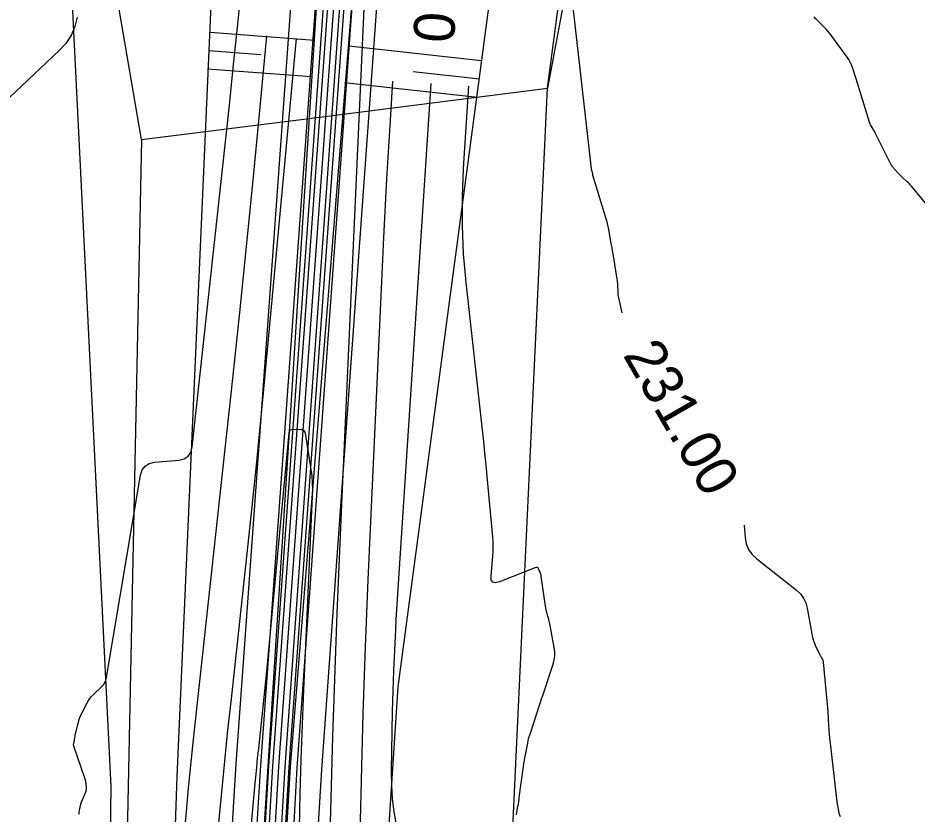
# Model space of a CAD drawing. Extents: x -534410 to -534262, y -1190162 to -1189584.
# Drawn here: x -534369.58 to -534347.56, y -1189654.72 to -1189635.21 of the extents above; entities that cross this region are included whole.
import ezdxf

# ---------------------------------------------------------------- set-up
doc = ezdxf.new("R2010")
doc.units = 0
for name, color, linetype in [('30', 7, 'Continuous'), ('31', 7, 'Continuous'), ('40', 7, 'Continuous'), ('_linie', 7, 'Continuous'), ('_N_osa', 7, 'Continuous'), ('_N_tenká', 7, 'Continuous'), ('_N_tenká_velmi', 7, 'Continuous'), ('_tenka', 7, 'Continuous'), ('_velmi_tenka', 7, 'Continuous'), ('Default', 7, 'Continuous'), ('Hranice parcel', 7, 'Continuous')]:
    doc.layers.add(name, color=color, linetype=linetype)

msp = doc.modelspace()

# ---------------------------------------------------------------- linework, layer by layer
at = {"layer": '30'}
for points in [[(-534356.77, -1189628.102), (-534355.551, -1189638.836), (-534355.548, -1189638.861), (-534355.544, -1189638.886), (-534355.54, -1189638.911), (-534355.534, -1189638.936), (-534355.512, -1189639.036), (-534355.507, -1189639.061), (-534355.5, -1189639.086), (-534355.494, -1189639.111), (-534355.486, -1189639.135), (-534355.19, -1189640.102), (-534355.169, -1189640.175), (-534355.15, -1189640.248), (-534355.134, -1189640.322), (-534355.119, -1189640.397), (-534355.066, -1189640.695), (-534355.053, -1189640.77), (-534355.04, -1189640.845), (-534355.028, -1189640.919), (-534355.015, -1189640.994), (-534354.914, -1189641.61), (-534354.909, -1189641.648), (-534354.904, -1189641.686), (-534354.901, -1189641.724), (-534354.899, -1189641.762), (-534354.893, -1189641.915), (-534354.891, -1189641.953), (-534354.887, -1189641.991), (-534354.881, -1189642.029), (-534354.874, -1189642.066), (-534354.791, -1189642.439)], [(-534361.953, -1189655.843), (-534361.869, -1189652.815), (-534361.764, -1189649.788), (-534361.638, -1189646.761), (-534360.829, -1189628.817)], [(-534368.091, -1189654.72), (-534368.087, -1189654.7), (-534368.084, -1189654.68), (-534368.066, -1189654.581), (-534368.061, -1189654.558), (-534368.057, -1189654.536), (-534368.047, -1189654.49), (-534368.044, -1189654.479), (-534368.041, -1189654.468), (-534368.037, -1189654.457), (-534368.033, -1189654.446), (-534367.919, -1189654.177), (-534367.911, -1189654.152), (-534367.905, -1189654.127), (-534367.903, -1189654.101), (-534367.904, -1189654.075), (-534367.916, -1189653.968), (-534367.919, -1189653.941), (-534367.924, -1189653.915), (-534367.931, -1189653.889), (-534367.939, -1189653.864), (-534368.214, -1189653.052), (-534368.218, -1189653.036), (-534368.22, -1189653.02), (-534368.22, -1189653.004), (-534368.218, -1189652.987), (-534368.202, -1189652.913), (-534368.2, -1189652.9), (-534368.198, -1189652.888), (-534368.196, -1189652.875), (-534368.194, -1189652.862), (-534368.187, -1189652.811), (-534368.185, -1189652.798), (-534368.183, -1189652.786), (-534368.18, -1189652.773), (-534368.177, -1189652.761), (-534368.099, -1189652.457), (-534368.083, -1189652.402), (-534368.065, -1189652.349), (-534368.043, -1189652.297), (-534368.019, -1189652.246), (-534367.891, -1189651.996), (-534367.858, -1189651.939), (-534367.822, -1189651.886), (-534367.781, -1189651.836), (-534367.735, -1189651.789), (-534367.534, -1189651.6), (-534367.489, -1189651.551), (-534367.454, -1189651.497), (-534367.428, -1189651.437), (-534367.412, -1189651.373), (-534366.581, -1189646.417), (-534366.541, -1189646.287), (-534366.47, -1189646.191), (-534366.368, -1189646.128), (-534366.236, -1189646.098), (-534365.644, -1189646.047), (-534365.512, -1189646.017), (-534365.414, -1189645.953), (-534365.348, -1189645.856), (-534365.316, -1189645.725), (-534364.406, -1189637.346), (-534364.301, -1189636.356), (-534364.199, -1189635.366), (-534364.1, -1189634.375)], [(-534362.766, -1189635.716), (-534363.58, -1189644.397), (-534363.668, -1189645.326), (-534363.76, -1189646.254), (-534363.856, -1189647.182), (-534363.955, -1189648.109), (-534364.357, -1189651.819), (-534364.456, -1189652.746), (-534364.55, -1189653.674), (-534364.64, -1189654.602), (-534364.726, -1189655.531)], [(-534359.474, -1189636.822), (-534360.283, -1189649.202), (-534360.298, -1189649.452), (-534360.313, -1189649.701), (-534360.326, -1189649.951), (-534360.338, -1189650.201), (-534360.383, -1189651.2), (-534360.393, -1189651.45), (-534360.402, -1189651.7), (-534360.409, -1189651.95), (-534360.414, -1189652.2), (-534360.439, -1189653.68), (-534360.436, -1189654.009), (-534360.415, -1189654.336), (-534360.376, -1189654.662), (-534360.319, -1189654.986)], [(-534351.799, -1189647.64), (-534351.772, -1189647.94), (-534351.743, -1189648.095), (-534351.686, -1189648.235), (-534351.6, -1189648.359), (-534351.485, -1189648.468), (-534350.515, -1189649.229), (-534350.417, -1189649.32), (-534350.34, -1189649.425), (-534350.284, -1189649.542), (-534350.248, -1189649.671), (-534350.118, -1189650.39), (-534350.107, -1189650.438), (-534350.093, -1189650.485), (-534350.076, -1189650.532), (-534350.056, -1189650.577), (-534349.939, -1189650.815), (-534349.931, -1189650.83), (-534349.924, -1189650.844), (-534349.916, -1189650.859), (-534349.908, -1189650.874), (-534349.876, -1189650.932), (-534349.868, -1189650.947), (-534349.863, -1189650.962), (-534349.859, -1189650.978), (-534349.856, -1189650.994), (-534349.755, -1189652.126), (-534349.749, -1189652.194), (-534349.744, -1189652.262), (-534349.739, -1189652.331), (-534349.734, -1189652.399), (-534349.71, -1189652.791), (-534349.709, -1189652.81), (-534349.707, -1189652.829), (-534349.704, -1189652.867), (-534349.702, -1189652.886), (-534349.7, -1189652.904), (-534349.525, -1189654.42), (-534349.512, -1189654.512), (-534349.495, -1189654.603), (-534349.473, -1189654.693), (-534349.446, -1189654.782)]]:
    msp.add_lwpolyline(points, dxfattribs=at)
at = {"layer": '31'}
for points in [[(-534368.133, -1189635.192), (-534368.19, -1189635.425), (-534368.283, -1189635.639), (-534368.409, -1189635.834), (-534368.571, -1189636.011), (-534371.025, -1189638.319)], [(-534347.156, -1189639.991), (-534347.694, -1189639.337), (-534347.719, -1189639.308), (-534347.745, -1189639.28), (-534347.772, -1189639.253), (-534347.8, -1189639.226), (-534347.913, -1189639.123), (-534347.942, -1189639.097), (-534347.969, -1189639.07), (-534347.996, -1189639.043), (-534348.022, -1189639.015), (-534348.125, -1189638.901), (-534348.149, -1189638.872), (-534348.172, -1189638.842), (-534348.192, -1189638.809), (-534348.211, -1189638.776), (-534348.587, -1189638.023), (-534348.598, -1189638.001), (-534348.609, -1189637.98), (-534348.622, -1189637.958), (-534348.634, -1189637.938), (-534348.685, -1189637.854), (-534348.698, -1189637.833), (-534348.708, -1189637.811), (-534348.718, -1189637.789), (-534348.726, -1189637.766), (-534348.99, -1189636.914), (-534349.055, -1189636.705), (-534349.142, -1189636.426), (-534349.166, -1189636.358), (-534349.196, -1189636.292), (-534349.231, -1189636.229), (-534349.272, -1189636.169), (-534349.671, -1189635.629), (-534349.708, -1189635.581), (-534349.746, -1189635.534), (-534349.787, -1189635.489), (-534349.828, -1189635.445), (-534350.007, -1189635.264), (-534350.045, -1189635.224), (-534350.082, -1189635.184)], [(-534365.595, -1189656.177), (-534365.451, -1189654.569), (-534365.414, -1189654.167), (-534365.375, -1189653.765), (-534365.334, -1189653.364), (-534365.291, -1189652.963), (-534364.324, -1189644.049), (-534364.151, -1189642.43), (-534363.984, -1189640.809), (-534363.824, -1189639.189), (-534363.669, -1189637.567), (-534363.489, -1189635.648)], [(-534360.41, -1189636.76), (-534360.47, -1189637.715), (-534360.553, -1189639.153), (-534360.629, -1189640.593), (-534360.697, -1189642.032), (-534361.011, -1189648.981), (-534361.079, -1189650.619), (-534361.135, -1189652.258), (-534361.181, -1189653.897), (-534361.215, -1189655.536)], [(-534357.374, -1189654.738), (-534357.336, -1189654.525), (-534357.327, -1189654.472), (-534357.318, -1189654.419), (-534357.31, -1189654.365), (-534357.303, -1189654.312), (-534357.199, -1189653.55), (-534357.189, -1189653.479), (-534357.177, -1189653.409), (-534357.165, -1189653.338), (-534357.152, -1189653.267), (-534357.097, -1189652.985), (-534357.083, -1189652.915), (-534357.066, -1189652.846), (-534357.046, -1189652.777), (-534357.025, -1189652.708), (-534356.741, -1189651.848), (-534356.737, -1189651.837), (-534356.475, -1189651.042), (-534356.448, -1189650.943), (-534356.435, -1189650.843), (-534356.435, -1189650.742), (-534356.448, -1189650.64), (-534356.549, -1189650.097), (-534356.556, -1189650.061), (-534356.564, -1189650.025), (-534356.573, -1189649.99), (-534356.583, -1189649.955), (-534356.623, -1189649.815), (-534356.633, -1189649.78), (-534356.641, -1189649.745), (-534356.648, -1189649.709), (-534356.654, -1189649.673), (-534356.767, -1189648.894), (-534356.771, -1189648.869), (-534356.777, -1189648.845), (-534356.785, -1189648.822), (-534356.793, -1189648.799), (-534356.832, -1189648.707), (-534356.843, -1189648.688), (-534356.858, -1189648.677), (-534356.876, -1189648.674), (-534356.897, -1189648.68), (-534357.792, -1189649.03), (-534357.888, -1189649.053), (-534357.954, -1189649.035), (-534357.989, -1189648.977), (-534357.994, -1189648.878), (-534357.952, -1189648.4), (-534357.944, -1189648.281), (-534357.941, -1189648.162), (-534357.944, -1189648.042), (-534357.953, -1189647.923), (-534358.089, -1189646.444), (-534358.116, -1189646.158), (-534358.144, -1189645.872), (-534358.174, -1189645.586), (-534358.205, -1189645.301), (-534358.606, -1189641.691), (-534358.668, -1189640.994), (-534358.699, -1189640.296), (-534358.699, -1189639.597), (-534358.669, -1189638.898), (-534358.538, -1189636.883)], [(-534365.3, -1189670.958), (-534363.781, -1189654.053), (-534363.759, -1189653.817), (-534363.737, -1189653.581), (-534363.713, -1189653.346), (-534363.688, -1189653.111), (-534363.586, -1189652.17), (-534363.56, -1189651.934), (-534363.536, -1189651.699), (-534363.513, -1189651.463), (-534363.49, -1189651.228), (-534362.943, -1189645.379), (-534362.933, -1189645.339), (-534362.913, -1189645.311), (-534362.883, -1189645.294), (-534362.842, -1189645.289), (-534362.659, -1189645.292), (-534362.618, -1189645.299), (-534362.586, -1189645.316), (-534362.565, -1189645.345), (-534362.553, -1189645.385), (-534362.411, -1189646.272), (-534362.389, -1189646.435), (-534362.375, -1189646.599), (-534362.37, -1189646.763), (-534362.374, -1189646.928), (-534362.588, -1189651.678), (-534362.623, -1189652.524), (-534362.652, -1189653.371), (-534362.676, -1189654.218), (-534362.693, -1189655.065)]]:
    msp.add_lwpolyline(points, dxfattribs=at)
at = {"layer": '_linie'}
for points in [[(-534366.12, -1189620.81), (-534364.52, -1189627.2), (-534365.69, -1189653.8), (-534366.76, -1189684.81), (-534368.14, -1189748.73), (-534368.38, -1189779.14), (-534368.65, -1189820.64), (-534368.59, -1189847.58), (-534367.2, -1189913.8)], [(-534363.12, -1189621.02), (-534362.79, -1189621.58), (-534361.82, -1189627.79), (-534363.46, -1189653.55), (-534365.47, -1189684.77), (-534366.65, -1189748.83), (-534366.75, -1189779.47), (-534366.9, -1189820.47), (-534366.95, -1189846.72), (-534366.338, -1189888.804), (-534363.85, -1189911.95), (-534357.07, -1189929.19), (-534352.334, -1189940.856)], [(-534359.03, -1189621.26), (-534359.41, -1189621.83), (-534360.84, -1189627.76), (-534362.92, -1189653.56), (-534364.64, -1189685), (-534365.94, -1189748.9), (-534366.02, -1189779.52), (-534366.03, -1189820.5), (-534366.48, -1189846.73), (-534365.511, -1189888.873), (-534362.72, -1189912.12), (-534356.62, -1189928.64), (-534351.589, -1189940.594)]]:
    msp.add_lwpolyline(points, dxfattribs=at)
at = {"layer": '_N_osa'}
msp.add_lwpolyline([(-534351.95, -1189940.722), (-534356.845, -1189928.915), (-534363.285, -1189912.035), (-534365.925, -1189888.838), (-534366.715, -1189846.725), (-534366.465, -1189820.485), (-534366.385, -1189779.495), (-534366.295, -1189748.865), (-534365.055, -1189684.885), (-534363.19, -1189653.555), (-534361.333, -1189627.822)], dxfattribs=at)
at = {"layer": '_N_tenká'}
for points in [[(-534352.92, -1189941.124), (-534357.821, -1189929.303), (-534364.313, -1189912.285), (-534366.973, -1189888.908), (-534367.765, -1189846.73), (-534367.515, -1189820.479), (-534367.435, -1189779.492), (-534367.345, -1189748.853), (-534366.104, -1189684.844), (-534364.238, -1189653.486), (-534362.424, -1189628.352), (-534361.782, -1189627.792)], [(-534350.98, -1189940.319), (-534355.869, -1189928.527), (-534362.257, -1189911.785), (-534364.876, -1189888.769), (-534365.665, -1189846.72), (-534365.415, -1189820.491), (-534365.335, -1189779.498), (-534365.245, -1189748.877), (-534364.006, -1189684.926), (-534362.142, -1189653.624), (-534360.329, -1189628.488), (-534360.884, -1189627.851)]]:
    msp.add_lwpolyline(points, dxfattribs=at)
at = {"layer": '_N_tenká_velmi'}
for points in [[(-534352.366, -1189940.894), (-534357.263, -1189929.081), (-534363.726, -1189912.142), (-534366.374, -1189888.868), (-534367.165, -1189846.727), (-534366.915, -1189820.482), (-534366.835, -1189779.494), (-534366.745, -1189748.86), (-534365.505, -1189684.867), (-534363.639, -1189653.525), (-534361.782, -1189627.792)], [(-534352.181, -1189940.817), (-534357.077, -1189929.007), (-534363.53, -1189912.095), (-534366.174, -1189888.855), (-534366.965, -1189846.726), (-534366.715, -1189820.484), (-534366.635, -1189779.494), (-534366.545, -1189748.862), (-534365.305, -1189684.875), (-534363.439, -1189653.539), (-534361.583, -1189627.805)], [(-534352.089, -1189940.779), (-534356.984, -1189928.97), (-534363.432, -1189912.071), (-534366.074, -1189888.848), (-534366.865, -1189846.726), (-534366.615, -1189820.484), (-534366.535, -1189779.495), (-534366.445, -1189748.863), (-534365.205, -1189684.879), (-534363.34, -1189653.545), (-534361.483, -1189627.812)], [(-534351.812, -1189940.664), (-534356.706, -1189928.86), (-534363.138, -1189911.999), (-534365.775, -1189888.828), (-534366.565, -1189846.724), (-534366.315, -1189820.486), (-534366.235, -1189779.495), (-534366.145, -1189748.867), (-534364.905, -1189684.891), (-534363.04, -1189653.565), (-534361.184, -1189627.831)], [(-534351.719, -1189940.626), (-534356.613, -1189928.823), (-534363.04, -1189911.975), (-534365.675, -1189888.822), (-534366.465, -1189846.724), (-534366.215, -1189820.486), (-534366.135, -1189779.496), (-534366.045, -1189748.868), (-534364.805, -1189684.895), (-534362.941, -1189653.571), (-534361.084, -1189627.838)], [(-534351.534, -1189940.549), (-534356.427, -1189928.749), (-534362.844, -1189911.928), (-534365.475, -1189888.808), (-534366.265, -1189846.723), (-534366.015, -1189820.488), (-534365.935, -1189779.496), (-534365.845, -1189748.87), (-534364.605, -1189684.903), (-534362.741, -1189653.585), (-534360.884, -1189627.851)]]:
    msp.add_lwpolyline(points, dxfattribs=at)
at = {"layer": '_tenka'}
for points in [[(-534349.13, -1189939.73), (-534354.63, -1189926.96), (-534362.03, -1189907.65), (-534364.521, -1189888.74), (-534364.47, -1189846.64), (-534364.29, -1189820.63), (-534364.22, -1189780.69), (-534363.18, -1189749.38), (-534362.5, -1189685.39), (-534360.27, -1189651.6), (-534357.03, -1189627.34), (-534354.77, -1189620.37)], [(-534366.12, -1189620.81), (-534364.52, -1189627.2), (-534365.69, -1189653.8), (-534366.76, -1189684.81), (-534368.14, -1189748.73), (-534368.38, -1189779.14), (-534368.65, -1189820.64), (-534368.59, -1189847.58), (-534367.2, -1189913.8)], [(-534366.12, -1189620.81), (-534364.52, -1189627.2), (-534365.69, -1189653.8), (-534366.76, -1189684.81), (-534368.14, -1189748.73), (-534368.38, -1189779.14), (-534368.65, -1189820.64), (-534368.59, -1189847.58), (-534367.2, -1189913.8)], [(-534363.12, -1189621.02), (-534362.79, -1189621.58), (-534361.82, -1189627.79), (-534363.46, -1189653.55), (-534365.47, -1189684.77), (-534366.65, -1189748.83), (-534366.75, -1189779.47), (-534366.9, -1189820.47), (-534366.95, -1189846.72), (-534366.338, -1189888.804), (-534363.85, -1189911.95), (-534357.07, -1189929.19), (-534352.334, -1189940.856)], [(-534363.12, -1189621.02), (-534362.79, -1189621.58), (-534361.82, -1189627.79), (-534363.46, -1189653.55), (-534365.47, -1189684.77), (-534366.65, -1189748.83), (-534366.75, -1189779.47), (-534366.9, -1189820.47), (-534366.95, -1189846.72), (-534366.338, -1189888.804), (-534363.85, -1189911.95), (-534357.07, -1189929.19), (-534352.334, -1189940.856)], [(-534359.03, -1189621.26), (-534359.41, -1189621.83), (-534360.84, -1189627.76), (-534362.92, -1189653.56), (-534364.64, -1189685), (-534365.94, -1189748.9), (-534366.02, -1189779.52), (-534366.03, -1189820.5), (-534366.48, -1189846.73), (-534365.511, -1189888.873), (-534362.72, -1189912.12), (-534356.62, -1189928.64), (-534351.589, -1189940.594)], [(-534359.03, -1189621.26), (-534359.41, -1189621.83), (-534360.84, -1189627.76), (-534362.92, -1189653.56), (-534364.64, -1189685), (-534365.94, -1189748.9), (-534366.02, -1189779.52), (-534366.03, -1189820.5), (-534366.48, -1189846.73), (-534365.511, -1189888.873), (-534362.72, -1189912.12), (-534356.62, -1189928.64), (-534351.589, -1189940.594)], [(-534368.65, -1189626.81), (-534368.65, -1189626.81), (-534367.31, -1189654.04), (-534367.67, -1189685.23), (-534369.56, -1189748.93), (-534369.48, -1189778.6), (-534369.45, -1189820.62), (-534369.45, -1189847.87), (-534371.206, -1189896.071), (-534372.39, -1189914.47)]]:
    msp.add_lwpolyline(points, dxfattribs=at)
at = {"layer": '_velmi_tenka'}
for p, q in [((-534364.873, -1189635.559), (-534362.321, -1189635.753)), ((-534358.232, -1189636.264), (-534361.483, -1189635.905)), ((-534364.907, -1189636.007), (-534363.631, -1189636.104)), ((-534364.942, -1189636.456), (-534362.39, -1189636.65)), ((-534358.282, -1189636.711), (-534359.907, -1189636.532)), ((-534358.331, -1189637.159), (-534361.582, -1189636.799))]:
    msp.add_line(p, q, dxfattribs=at)
at = {"layer": 'Default'}
for p, q in [((-534368.65, -1189626.81), (-534367.31, -1189654.04)), ((-534367.31, -1189654.04), (-534367.67, -1189685.23))]:
    msp.add_line(p, q, dxfattribs=at)
msp.add_lwpolyline([(-534349.13, -1189939.73), (-534354.63, -1189926.96), (-534362.03, -1189907.65), (-534364.521, -1189888.74), (-534364.47, -1189846.64), (-534364.29, -1189820.63), (-534364.22, -1189780.69), (-534363.18, -1189749.38), (-534362.5, -1189685.39), (-534360.27, -1189651.6), (-534357.03, -1189627.34), (-534354.77, -1189620.37)], dxfattribs=at)
at = {"layer": 'Hranice parcel'}
for p, q in [((-534366.56, -1189638.19), (-534368.76, -1189625.38)), ((-534359.48, -1189697.97), (-534356.61, -1189636.93)), ((-534366.56, -1189638.19), (-534367.77, -1189697.34))]:
    msp.add_line(p, q, dxfattribs=at)
for points in [[(-534356.61, -1189636.93), (-534352.14, -1189603.1), (-534349.757, -1189584.47)], [(-534347.83, -1189584.47), (-534354.43, -1189625.3), (-534356.61, -1189636.93)], [(-534366.56, -1189638.19), (-534362.58, -1189637.69), (-534356.61, -1189636.93)]]:
    msp.add_lwpolyline(points, dxfattribs=at)

# ---------------------------------------------------------------- texts
at = {"layer": '40'}
for s, rotation, p in [('230.00', 266.2644, (-534359.641, -1189631.698)), ('231.00', 300.0371, (-534354.779, -1189643.469))]:
    msp.add_text(s, height=1, rotation=rotation, dxfattribs=at).set_placement(p)

doc.saveas('drawing.dxf')
